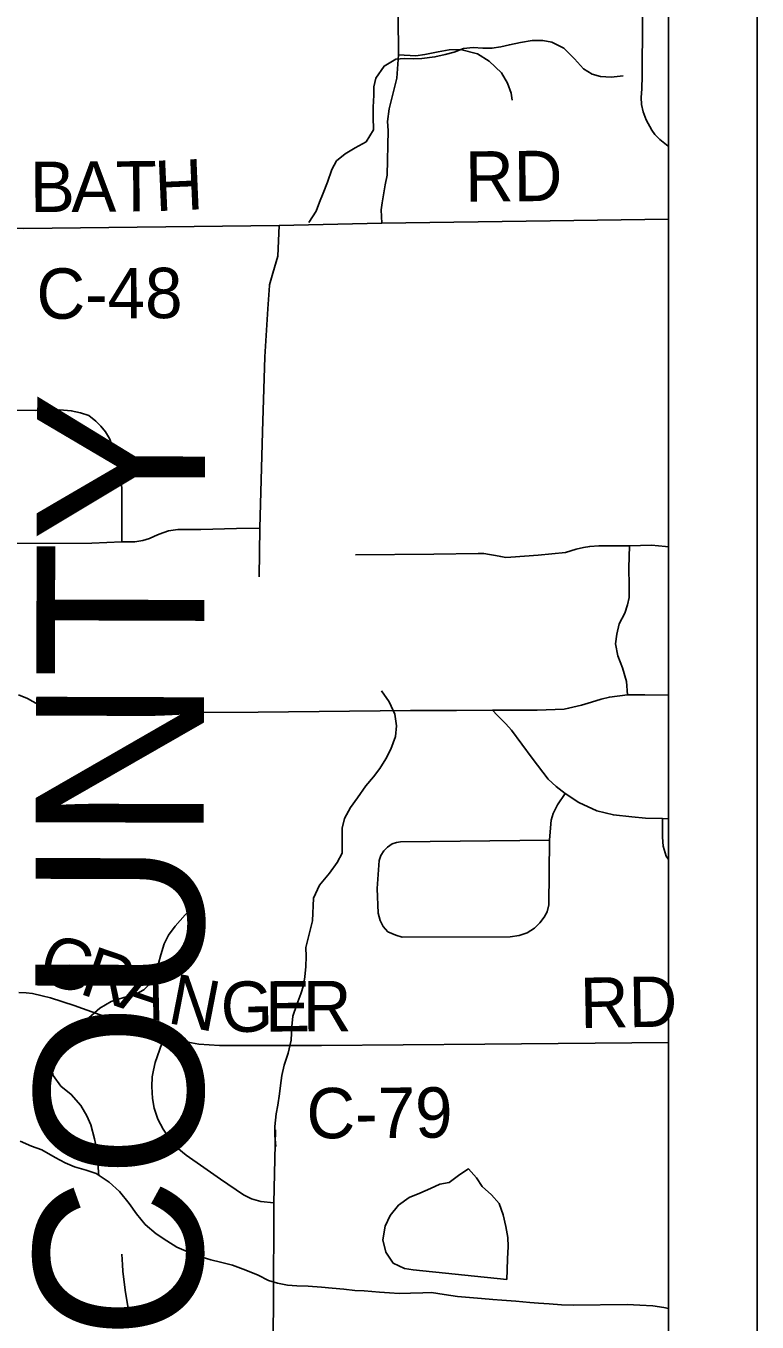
# Model space of a CAD drawing. Extents: x 0 to 34, y 0 to 22.
# Drawn here: x 8.175 to 9, y 15.589 to 17.051 of the extents above; entities that cross this region are included whole.
import ezdxf

# ---------------------------------------------------------------- set-up
doc = ezdxf.new("R2010")
doc.units = 0
for name, color, linetype in [('GM_X_Corporation', 7, 'Continuous'), ('GM_X_County_Road', 7, 'Continuous'), ('GM_X_County_Road_Text', 7, 'Continuous'), ('GM_X_County_Text', 7, 'Continuous'), ('GM_X_Minor_Lake', 7, 'Continuous'), ('GM_X_Minor_River', 7, 'Continuous'), ('GM_X_Township_Road', 7, 'Continuous'), ('SH_Data', 7, 'Continuous')]:
    doc.layers.add(name, color=color, linetype=linetype)

msp = doc.modelspace()

# ---------------------------------------------------------------- linework, layer by layer
at = {"layer": 'GM_X_Corporation'}
for points in [[(7.9901, 18.1613), (7.991, 17.7727), (7.9891, 17.5498), (7.9877, 17.3871), (7.9838, 16.7968), (7.9825, 16.6077), (7.9818, 16.3982), (7.9825, 16.3395), (7.9821, 16.2487), (7.9807, 15.9078), (7.9808, 15.7192), (7.979, 15.5988), (7.9792, 15.5481), (7.9765, 15.2637), (7.9726, 14.5453), (7.9734, 14.1), (8.9, 14.1), (8.9, 20.9)], [(7.9901, 18.1613), (7.991, 17.7727), (7.9891, 17.5498), (7.9877, 17.3871), (7.9838, 16.7968), (7.9825, 16.6077), (7.9818, 16.3982), (7.9825, 16.3395), (7.9821, 16.2487), (7.9807, 15.9078), (7.9808, 15.7192), (7.979, 15.5988), (7.9792, 15.5481), (7.9765, 15.2637), (7.9726, 14.5453), (8.3169, 14.5418), (8.5518, 14.5426), (8.5844, 14.5431), (8.8409, 14.5545), (8.9, 14.5547), (8.9, 19.1229)]]:
    msp.add_lwpolyline(points, dxfattribs=at)
at = {"layer": 'GM_X_County_Road'}
for points in [[(7.9845, 16.7962), (8.0423, 16.8166), (8.0561, 16.8201), (8.0688, 16.8228), (8.0916, 16.8232), (8.1729, 16.8224), (8.4609, 16.8258), (8.5768, 16.8284), (8.7668, 16.8308), (8.9, 16.8327)], [(8.1676, 15.9607), (8.1758, 15.9604), (8.1829, 15.9597), (8.1937, 15.9573), (8.2033, 15.9547), (8.2298, 15.9461), (8.278, 15.929), (8.3106, 15.9171), (8.3314, 15.9108), (8.3462, 15.9071), (8.3622, 15.9041), (8.3705, 15.9028), (8.382, 15.9018), (8.3938, 15.9011), (8.4756, 15.9011), (8.5087, 15.9012), (8.6929, 15.9027), (8.9, 15.9044)]]:
    msp.add_lwpolyline(points, dxfattribs=at)
at = {"layer": 'GM_X_Minor_Lake'}
for points in [[(8.7177, 15.6374), (8.718, 15.648), (8.7186, 15.6606), (8.7192, 15.6743), (8.7191, 15.6845), (8.7168, 15.697), (8.7136, 15.7103), (8.7093, 15.7228), (8.7005, 15.7326), (8.6898, 15.742), (8.6836, 15.7518), (8.6744, 15.762), (8.6646, 15.7558), (8.6526, 15.7466), (8.6423, 15.7446), (8.6317, 15.7399), (8.6197, 15.7345), (8.6076, 15.7298), (8.5955, 15.721), (8.5861, 15.7095), (8.5805, 15.6973), (8.578, 15.682), (8.5812, 15.668), (8.5896, 15.6556), (8.6022, 15.6496), (8.6121, 15.6482)], [(8.6121, 15.6482), (8.7177, 15.6374)]]:
    msp.add_lwpolyline(points, dxfattribs=at)
at = {"layer": 'GM_X_Minor_River'}
for points in [[(8.4944, 16.8291), (8.5027, 16.8417), (8.5064, 16.852), (8.5108, 16.8623), (8.5157, 16.8745), (8.5205, 16.889), (8.5257, 16.8985), (8.5355, 16.9066), (8.5468, 16.9132), (8.5593, 16.9201), (8.5675, 16.9335), (8.567, 16.9483), (8.5669, 16.9593), (8.5679, 16.9726), (8.5678, 16.9821), (8.57, 16.992), (8.5794, 17.0054), (8.5926, 17.0131), (8.6024, 17.014), (8.6123, 17.0137), (8.6218, 17.0142), (8.6366, 17.0158), (8.6483, 17.0186), (8.6585, 17.0213), (8.6688, 17.0252), (8.6797, 17.0265), (8.6908, 17.0258), (8.701, 17.0255), (8.7109, 17.0272), (8.7207, 17.0295), (8.7332, 17.0319), (8.7465, 17.0343), (8.7582, 17.0344), (8.7685, 17.0326), (8.7822, 17.0255), (8.7941, 17.0135), (8.8041, 17.0022), (8.814, 16.9962), (8.8235, 16.9936), (8.8353, 16.993), (8.8489, 16.9943)], [(8.4571, 15.7873), (8.4563, 15.7998), (8.4562, 15.8097), (8.4576, 15.8241), (8.4594, 15.834), (8.4615, 15.8466), (8.4626, 15.8561), (8.464, 15.8671), (8.4666, 15.8789), (8.471, 15.8923), (8.4747, 15.9071), (8.4753, 15.9227), (8.4763, 15.9341), (8.4811, 15.9475), (8.4856, 15.9593), (8.4885, 15.9688), (8.49, 15.9787), (8.491, 15.9901), (8.4913, 16.0015), (8.4912, 16.0118), (8.4945, 16.0251), (8.4985, 16.0415), (8.4998, 16.0673), (8.5065, 16.0818), (8.5177, 16.0956), (8.5264, 16.1075), (8.532, 16.1178), (8.5322, 16.1303), (8.5321, 16.1463), (8.5346, 16.157), (8.5414, 16.1696), (8.5492, 16.1803), (8.5586, 16.194), (8.5676, 16.204), (8.5744, 16.2136), (8.5815, 16.2243), (8.5871, 16.2353), (8.5923, 16.2494), (8.5933, 16.2616), (8.5916, 16.2749), (8.5851, 16.2885), (8.5766, 16.301)], [(8.2575, 15.7551), (8.2574, 15.7577), (8.2565, 15.7721), (8.2549, 15.7854), (8.2529, 15.796), (8.2486, 15.8115), (8.2443, 15.8218), (8.2374, 15.8335), (8.2266, 15.8459), (8.2148, 15.8553), (8.206, 15.8674), (8.2032, 15.8818), (8.2054, 15.8924), (8.2117, 15.9028), (8.2215, 15.912), (8.2328, 15.9208), (8.2433, 15.9297), (8.2588, 15.9431), (8.2716, 15.9508), (8.286, 15.9551), (8.2985, 15.9587), (8.3083, 15.9637), (8.3181, 15.9737), (8.3229, 15.9836), (8.3251, 15.9935), (8.3277, 16.0034), (8.3314, 16.0156), (8.3362, 16.0255), (8.3437, 16.0355), (8.355, 16.0485), (8.3663, 16.0604)], [(8.9, 15.6044), (8.8948, 15.6056), (8.8823, 15.6074), (8.8678, 15.6084), (8.8534, 15.609), (8.7931, 15.6085), (8.7794, 15.6087), (8.7657, 15.6097), (8.7536, 15.6107), (8.7437, 15.6114), (8.7278, 15.6128), (8.7122, 15.6141), (8.7019, 15.6148), (8.6894, 15.6158), (8.6757, 15.6168), (8.6621, 15.6182), (8.6472, 15.6204), (8.6328, 15.6225), (8.6229, 15.6224), (8.6093, 15.6219), (8.5964, 15.6214), (8.5854, 15.6221), (8.574, 15.6231), (8.5569, 15.6245), (8.5463, 15.6247), (8.5341, 15.6262), (8.5208, 15.6275), (8.5087, 15.6286), (8.4938, 15.6296), (8.4809, 15.6302), (8.4703, 15.6309), (8.4593, 15.633), (8.449, 15.636), (8.4372, 15.642), (8.4235, 15.6479), (8.4083, 15.6535), (8.3949, 15.6568), (8.3839, 15.6593), (8.3694, 15.6641), (8.3588, 15.6682), (8.3458, 15.6738), (8.3344, 15.6809), (8.3225, 15.6888), (8.3099, 15.6993), (8.3003, 15.7113), (8.2919, 15.723), (8.2811, 15.7366), (8.2693, 15.7471), (8.2548, 15.7569), (8.2433, 15.7606), (8.2304, 15.7643), (8.2197, 15.7687), (8.2083, 15.7747), (8.1934, 15.7833), (8.1816, 15.7877), (8.1691, 15.7933)]]:
    msp.add_lwpolyline(points, dxfattribs=at)
at = {"layer": 'GM_X_Township_Road'}
for points in [[(8.5955, 17.018), (8.5952, 17.0623), (8.5962, 17.1341), (8.5973, 17.1627), (8.6024, 17.1764), (8.6099, 17.1893), (8.6194, 17.1995), (8.6279, 17.206), (8.6429, 17.2138), (8.6585, 17.2179), (8.6756, 17.2179), (8.6865, 17.2155), (8.6943, 17.2128)], [(8.9, 16.9151), (8.8998, 16.9152), (8.8905, 16.9226), (8.8848, 16.9283), (8.8813, 16.9333), (8.8749, 16.9447), (8.8717, 16.9539), (8.8698, 16.962), (8.8694, 16.97), (8.87, 16.9799), (8.8703, 16.9945), (8.871, 17.1184)], [(8.5768, 16.8284), (8.5761, 16.8433), (8.5772, 16.8512), (8.5806, 16.8716), (8.5829, 16.8825), (8.584, 16.9329), (8.5833, 16.9431), (8.585, 16.9574), (8.5908, 16.9799), (8.5938, 16.9918), (8.5955, 17.018)], [(8.5955, 17.018), (8.615, 17.017), (8.6252, 17.0184), (8.6402, 17.0214), (8.6528, 17.0238), (8.6654, 17.0242), (8.6848, 17.0194), (8.6977, 17.0112), (8.7117, 16.9979), (8.7185, 16.9864), (8.7226, 16.9751), (8.7239, 16.967)], [(8.4503, 16.759), (8.4539, 16.7721), (8.4597, 16.791), (8.4609, 16.8258)], [(8.4384, 16.4294), (8.4392, 16.4844), (8.4423, 16.593), (8.4447, 16.6777), (8.4481, 16.7319), (8.4501, 16.7581), (8.4503, 16.759)], [(8.2836, 16.4691), (8.2836, 16.5301), (8.2817, 16.5425), (8.278, 16.5574), (8.2748, 16.5722), (8.2697, 16.5855), (8.2652, 16.593), (8.26, 16.5996), (8.2543, 16.6051), (8.2463, 16.6114), (8.237, 16.6146), (8.2266, 16.6169), (8.2137, 16.6178), (8.1868, 16.6171), (8.1292, 16.6177)], [(8.1151, 16.4672), (8.2497, 16.4676), (8.2836, 16.4691), (8.2983, 16.469), (8.3072, 16.4704), (8.3148, 16.4727), (8.3204, 16.4754), (8.3257, 16.4778), (8.3363, 16.4814), (8.3466, 16.483), (8.3726, 16.4831), (8.4128, 16.4841), (8.4392, 16.4844)], [(8.5473, 16.4545), (8.6353, 16.4552), (8.6853, 16.4558), (8.6917, 16.4558), (8.6982, 16.4549), (8.7051, 16.4535), (8.7109, 16.4524), (8.7166, 16.4515), (8.7224, 16.4519), (8.7532, 16.454), (8.7839, 16.457), (8.7959, 16.4607), (8.8044, 16.4625), (8.8113, 16.4639), (8.8214, 16.4646), (8.8562, 16.4644), (8.8809, 16.4651), (8.8968, 16.4639), (8.9, 16.4634)], [(8.8537, 16.2964), (8.8528, 16.3116), (8.8484, 16.3268), (8.8429, 16.3404), (8.8403, 16.3542), (8.8419, 16.3648), (8.8445, 16.3764), (8.8507, 16.3886), (8.8539, 16.398), (8.8558, 16.4063), (8.8558, 16.4194), (8.8555, 16.4397), (8.8562, 16.4644)], [(8.1672, 16.2964), (8.1771, 16.2923), (8.1893, 16.2858), (8.1992, 16.2815), (8.2077, 16.2778), (8.2153, 16.2762), (8.248, 16.2759), (8.3526, 16.2766), (8.4374, 16.2768), (8.6091, 16.2789), (8.6612, 16.2789), (8.7016, 16.2794), (8.7067, 16.2736), (8.7168, 16.2639), (8.7231, 16.2568), (8.7463, 16.225), (8.7645, 16.2015), (8.7733, 16.193), (8.7837, 16.1852), (8.7991, 16.1753), (8.8191, 16.1656), (8.838, 16.1612), (8.8588, 16.1589), (8.8742, 16.1575), (8.8933, 16.1571), (8.9, 16.1566)], [(8.7016, 16.2794), (8.7519, 16.2794), (8.7825, 16.2805), (8.7875, 16.2814), (8.8021, 16.2847), (8.8134, 16.2884), (8.824, 16.2918), (8.8334, 16.2939), (8.8537, 16.2964), (8.8733, 16.2967), (8.9, 16.2963)], [(8.5717, 16.078), (8.5726, 16.0504), (8.5749, 16.0421), (8.5784, 16.0354), (8.5837, 16.0294), (8.5927, 16.0257), (8.5996, 16.0232), (8.7215, 16.0237), (8.7316, 16.0253), (8.7408, 16.028), (8.7489, 16.0333), (8.7549, 16.0396), (8.7599, 16.046), (8.7634, 16.052), (8.765, 16.0598), (8.7659, 16.1326), (8.7671, 16.1465), (8.7678, 16.1552), (8.7701, 16.1628), (8.7749, 16.1725), (8.7837, 16.1852)], [(8.9, 16.1108), (8.8975, 16.1147), (8.8942, 16.126), (8.8933, 16.1359), (8.8933, 16.1571)], [(8.7659, 16.1326), (8.5977, 16.1306), (8.5934, 16.1301), (8.5885, 16.1285), (8.5832, 16.1246), (8.5789, 16.1207), (8.5756, 16.1154), (8.5738, 16.1098), (8.5717, 16.078)], [(8.4549, 15.7237), (8.4404, 15.7253), (8.43, 15.7283), (8.4208, 15.7327), (8.3948, 15.7504), (8.3761, 15.7636), (8.3563, 15.7774), (8.3457, 15.7862), (8.3374, 15.7961), (8.3303, 15.8069), (8.3241, 15.8182), (8.3199, 15.8304), (8.3181, 15.8413), (8.3174, 15.8547), (8.3179, 15.8657), (8.3192, 15.8733), (8.3212, 15.882), (8.3314, 15.9108)], [(8.4531, 15.4157), (8.4538, 15.5102), (8.454, 15.5528), (8.4547, 15.6078), (8.4549, 15.7237), (8.4568, 15.806)], [(8.2913, 15.588), (8.2911, 15.5972), (8.2902, 15.6067), (8.2874, 15.6254), (8.2847, 15.6468), (8.2845, 15.6539), (8.2837, 15.6657)]]:
    msp.add_lwpolyline(points, dxfattribs=at)
at = {"layer": 'SH_Data'}
for p, q in [((9, 21), (9, 14)), ((8.9, 20.9), (8.9, 14.1))]:
    msp.add_line(p, q, dxfattribs=at)

# ---------------------------------------------------------------- texts
at = {"layer": 'GM_X_County_Road_Text'}
for s, height, rotation, p in [('RD', 0.05682, 0.4955, (8.6709, 16.8525)), ('B', 0.0568, 0.3083, (8.1801, 16.8408)), ('A', 0.0568, 0.3153, (8.2268, 16.841)), ('T', 0.0568, 0.6036, (8.2771, 16.8413)), ('H', 0.0568, 2.4379, (8.3216, 16.8418)), ('C-48', 0.05682, 0.3442, (8.1875, 16.7204)), ('G', 0.0568, 343.2039, (8.1866, 15.9744)), ('R', 0.0568, 341.1627, (8.234, 15.9601)), ('A', 0.0568, 341.2483, (8.2782, 15.945)), ('N', 0.0568, 348.9814, (8.3336, 15.9268)), ('RD', 0.05682, 0.9891, (8.8007, 15.9207)), ('G', 0.0568, 0.8495, (8.3955, 15.9161)), ('E', 0.0568, 0.3, (8.4454, 15.9168)), ('R', 0.0568, 0.3024, (8.4879, 15.917)), ('C-79', 0.05682, 0.3439, (8.492, 15.7963))]:
    msp.add_text(s, height=height, rotation=rotation, dxfattribs=at).set_placement(p)
at = {"layer": 'GM_X_County_Text'}
msp.add_text('SUMMIT COUNTY', height=0.189394, rotation=89.8023, dxfattribs=at).set_placement((8.3702, 14.4995))

doc.saveas('drawing.dxf')
